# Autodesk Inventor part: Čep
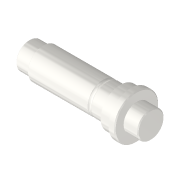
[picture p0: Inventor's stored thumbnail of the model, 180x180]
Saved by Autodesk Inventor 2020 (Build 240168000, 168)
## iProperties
Created: 2025-03
Part Number: Čep
Material: Ocel
Document SubType Name: Modeling
Designer: doma
Density: 7.85 g/cm^3
Appearance: Ocel
Mass: 1078.88 g
Surface Area: 196.98 cm^2
Volume: 137.437 cm^3
Author: doma
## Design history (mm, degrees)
sketch "Náčrt1"
  geometry: L1 (0, 0)-(0, 15); L2 (0, 15)-(115, 15); L3 (115, 15)-(115, 25); L4 (115, 25)-(122, 25); L5 (122, 25)-(122, 15); L6 (122, 15)-(138, 15); L7 (138, 15)-(138, 0); L8 (138, 0)-(0, 0); L9 (16, 15)-(16, 17.5); L10 (16, 17.5)-(103, 17.5); L11 (103, 17.5)-(103, 22); L12 (103, 22)-(115, 22); A1 r 5 centre (86, 22) between (83.821, 17.5) and (88.179, 17.5)
  constraints: 24 end point, 9 perpendicular, 4 point on line, 3 vertical, 2 point on circle, 1 centre point, 1 collinear
  dimensions: "d0" = 15 distance of L1.start L1.end; "d1" = 115 distance of L1.end L2.end; "d3" = 7 distance of L3.end L4.end; "d5" = 16 distance of L5.end L6.end; "d6" = 25 distance between parallel lines of L8 L4; "d15" = 17.5 distance between parallel lines of L8 L10; "d16" = 22 distance between parallel lines of L8 L12; "d18" = 16 distance between parallel lines of L9 L1; "d19" = 87 distance of L9.end L10.end; "d22" = 5 radius of A1; "d23" = 22 distance from line of L8 A1.centre; "d24" = 17 distance from line of L11 A1.centre
revolve "Rotace1" sketch "Náčrt1" stored, may be unused: angle "d7" = 90 deg
sketch "Náčrt2"
  geometry: 2 further points
hole "Díra1" sketch "Náčrt2" at (0, 0) diameter "d8" = 6.647; stored, may be unused: countersink angle "d12" = 90 deg, drill point angle "d14" = 118 deg; dims "d9" = 15, "d10" = 4, "d11" = 2, "d13" = 20
fillet "Zaoblení1" dims "d25" = 0.2
chamfer "Zkosení1" distance "d26" = 1; stored, may be unused: second distance "d27" = 2, angle "d28" = 45 deg
chamfer "Zkosení2" distance "d29" = 0.5; stored, may be unused: second distance "d30" = 2, angle "d31" = 45 deg
node "Těleso1"
